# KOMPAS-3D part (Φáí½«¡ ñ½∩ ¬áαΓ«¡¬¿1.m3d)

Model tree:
1. Эскиз:1
2. Операция выдавливания:1
     Толщина стенки 2 = 6; Расстояние 1 = 0.6
3. Эскиз:2
4. Операция выдавливания:2
     Толщина стенки 1 = 12; Толщина стенки 2 = 12; Расстояние 1 = 0.6; Расстояние 2 = 0.6
5. Эскиз:3
6. Операция выдавливания:3
     Толщина стенки 1 = 12; Толщина стенки 2 = 12; Расстояние 1 = 0.6; Расстояние 2 = 0.6
7. Эскиз:4
8. Операция выдавливания:4
     Толщина стенки 1 = 35; Толщина стенки 2 = 35; Расстояние 1 = 0.6; Расстояние 2 = 0.6
9. Эскиз:5
10. Вырезать элемент выдавливания:1
     Расстояние 1 = 10
11. Эскиз:6
12. Вырезать элемент выдавливания:2
     Расстояние 1 = 10
